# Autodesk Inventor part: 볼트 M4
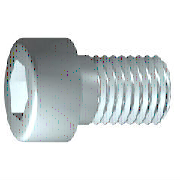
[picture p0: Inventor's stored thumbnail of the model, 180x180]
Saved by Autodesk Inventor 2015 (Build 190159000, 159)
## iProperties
IsCustomPart: 0
Created: 2012-02
Part Number: 볼트 M4
Material: 스테인리스강
Description: 6각 소켓 머리 캡 나사
Document SubType Name: Modeling
Standard: ISO 4762
Designer: mduedu
Standard Revision: Fourth edition 2004-03-01
Standards Organization: ISO
Language: ko-KR
Size Designation: M4 x 12
Categories: <MemberInstance><Categories><Category DisplayName="조임쇠" InternalName="e4da775c-781d-43d5-af7c-5136215cf5a6" Mnemonic="FSTN"><Category DisplayName="볼트" InternalN
Density: 8.08 g/cm^3
Mass: 2.2972 g
Surface Area: 3.30853 cm^2
Volume: 0.284306 cm^3
Appearance: 반광택
Author: mduedu
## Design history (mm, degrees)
sketch "스케치1"
  geometry: L1 (-1, 0)-(12, 0); L2 (12, 0)-(12, 2); L3 (12, 2)-(1.75, 2); L4 (1.75, 2)-(1.32, 2); L5 (1.32, 2)-(0, 2); L6 (0, 2)-(0, 3.5); L7 (0, 3.5)-(-4, 3.5); L8 (-4, 3.5)-(-4, 1.732); L9 (-4, 1.732)-(-2, 1.732); L10 (-2, 1.732)-(-1, 0); L11 (-7.2, 0)-(15.2, 0) reference; L12 (0, -0.7)-(0, 4.2) reference; L13 (1.75, 2)-(0, 2)
  constraints: 22 end point, 6 parallel, 2 collinear, 2 perpendicular, 1 horizontal, 1 point on line
  dimensions: "d1" = 10.25 distance from line of L3.end L2 (= GEL); "d2" = 0.42952 distance of L4.end L3.end (computed from GAL); "d3" = 4 distance between parallel lines of L8 L6 (= KOH); "d4" = 2 distance of L8.end L9.end (= INTI); "d5" = 60 deg angle of L10 L1; "d6" = 4 diameter of L3 L1 (= GD); "d7" = 4 diameter of L5 L1 (= BDM); "d8" = 3.4641 diameter of L9 L1 (= 1.1547 x SW); "d9" = 7 diameter of L7 L1 (= KOD); "d26" = 12 distance between parallel lines of L12 L2 (= NLG)
revolve "본체" sketch "스케치1" stored, may be unused: angle "d10" = 90 deg
sketch "스케치2"
  geometry: L1 (0, -4.9)-(0, 4.9) reference; L2 (-4.9, 0)-(4.9, 0) reference; L3 (1.732, 0)-(0.866, -1.5); L4 (0.866, -1.5)-(-0.866, -1.5); L5 (-0.866, -1.5)-(-1.732, 0); L6 (-1.732, 0)-(-0.866, 1.5); L7 (-0.866, 1.5)-(0.866, 1.5); L8 (0.866, 1.5)-(1.732, 0); 2 further points
  constraints: 12 end point, 1 coincident, 1 horizontal alignment, 1 point on line, 12 other
extrude "슬롯" join sketch "스케치2" stored distance "d11" = 10; taper "d12" = 0 deg
workplane "Work Plane1"
fillet "Fillet2" dims "d30" = 0.1 (= R)
body "Solid1"
fillet "모깎기1" dims "d17" = 0.4 (= RR)
feature "스레드" dims "d13" = 10.25 (= GEL), "d14" = 0
chamfer "모따기1" distance "d15" = 0.42941 (= -0.5 x SPD + 0.5 x GD); stored, may be unused: second distance "d16" = 0.42941 (= GUL), angle "d27" = 45 deg
other parameters: "GD" = 4 [user parameter; used in 2 equation terms], "NLG" = 12 [user parameter; used in 1 equation term], "GEL" = 10.25 [user parameter; used in 2 equation terms], "KOD" = 7 [user parameter; used in 1 equation term], "KOH" = 4 [user parameter; used in 1 equation term], "INTI" = 2 [user parameter; used in 1 equation term], "GAL" = 0.42941 (= 0.61345 x PTC) [user parameter; used in 1 equation term], "GUL" = 0.42941 (= 0.61345 x PTC) [user parameter; used in 1 equation term], "BDM" = 4 (= NND) [user parameter; used in 1 equation term], "SW" = 3 [user parameter; used in 2 equation terms], "RR" = 0.4 [user parameter; used in 1 equation term], "SPD" = 3.14117 (= NND - 1.2269 x PTC) [user parameter; used in 1 equation term], "d19" = 0, "d28" = 0, "d29" = 0, "R" = 0.1 [user parameter; used in 1 equation term], "TOA" = 30 deg [user parameter], "GD1" = 3.14117 (= THREADDIA - 1.2269 x PTC) [user parameter], "THREADDIA" = 4 [user parameter; used in 1 equation term], "FAWI" = 45 deg [user parameter], "TPU" = 14.28571 (computed from PTC) [user parameter], "PTC" = 0.7 [user parameter; used in 5 equation terms], "NND" = 4 [user parameter; used in 2 equation terms], "E0" = 3.465 (= 1.155 x SW) [user parameter]
